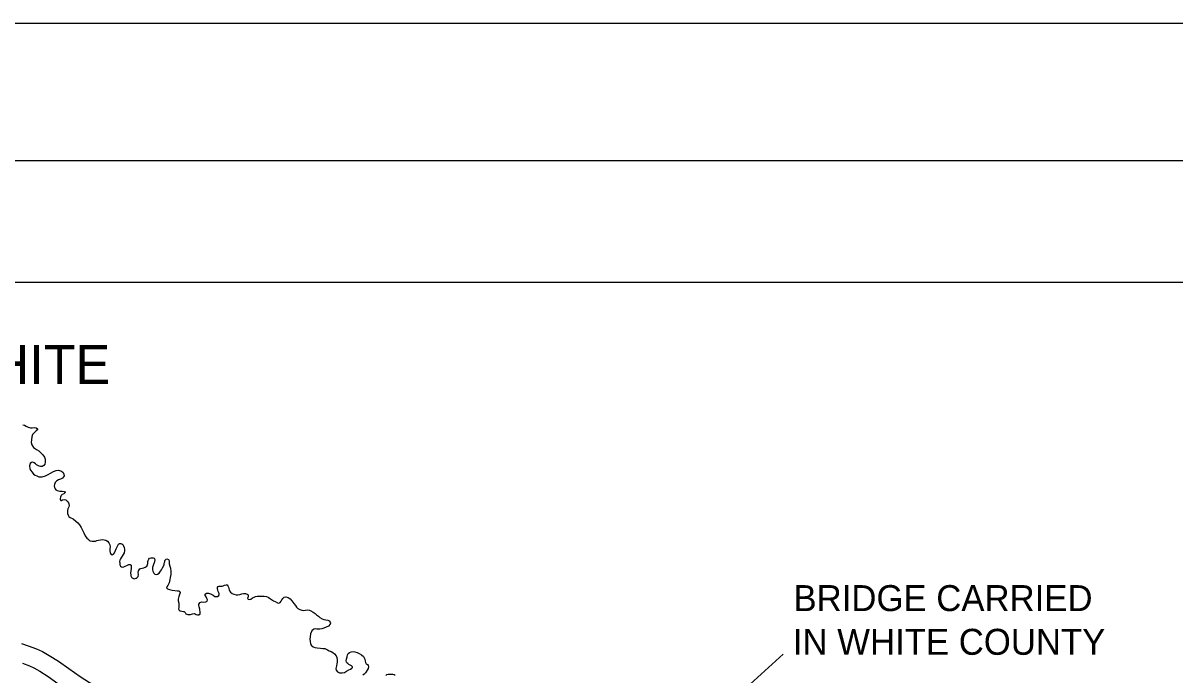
# Model space of a CAD drawing. Extents: x 1367863 to 1368197, y 380048 to 380261.
# Drawn here: x 1367891.07 to 1367923.7, y 380242.97 to 380261.43 of the extents above; entities that cross this region are included whole.
import ezdxf

# ---------------------------------------------------------------- set-up
doc = ezdxf.new("R2010")
doc.units = 0
for name, color, linetype in [('Level 10', 7, 'Continuous'), ('Level 2', 7, 'Continuous'), ('Level 30', 7, 'Continuous'), ('R_Border', 7, 'Continuous'), ('R_No Plot', 7, 'Continuous')]:
    doc.layers.add(name, color=color, linetype=linetype)

msp = doc.modelspace()

# ---------------------------------------------------------------- linework, layer by layer
at = {"layer": 'Level 10'}
for points in [[(1367891.032, 380243.854), (1367891.22, 380243.794), (1367891.456, 380243.711), (1367891.621, 380243.63), (1367891.816, 380243.521), (1367892.075, 380243.361), (1367892.365, 380243.153), (1367892.691, 380242.923), (1367892.954, 380242.757), (1367893.176, 380242.635), (1367893.378, 380242.527), (1367893.584, 380242.429), (1367893.807, 380242.311), (1367894.073, 380242.155), (1367894.149, 380242.124), (1367894.269, 380242.066), (1367894.803, 380241.868)], [(1367891.055, 380243.298), (1367891.254, 380243.229), (1367891.378, 380243.168), (1367891.551, 380243.071), (1367891.785, 380242.926), (1367892.062, 380242.728), (1367892.4, 380242.488), (1367892.689, 380242.307), (1367892.927, 380242.176), (1367893.142, 380242.061), (1367893.349, 380241.962), (1367893.553, 380241.854), (1367893.842, 380241.684), (1367893.938, 380241.646), (1367894.062, 380241.585), (1367894.621, 380241.378)]]:
    msp.add_lwpolyline(points, dxfattribs=at)
at = {"layer": 'Level 2'}
for points in [[(1367891.062, 380250.05), (1367891.116, 380250.043), (1367891.159, 380250.013), (1367891.217, 380249.985), (1367891.28, 380249.969), (1367891.329, 380249.966), (1367891.386, 380249.974), (1367891.442, 380249.966), (1367891.486, 380249.934), (1367891.482, 380249.906), (1367891.443, 380249.877), (1367891.397, 380249.835), (1367891.345, 380249.776), (1367891.321, 380249.711), (1367891.308, 380249.625), (1367891.306, 380249.553), (1367891.322, 380249.484), (1367891.373, 380249.412), (1367891.453, 380249.355), (1367891.517, 380249.312), (1367891.58, 380249.256), (1367891.63, 380249.203), (1367891.676, 380249.135), (1367891.7, 380249.075), (1367891.703, 380248.991), (1367891.694, 380248.942), (1367891.662, 380248.899), (1367891.612, 380248.869), (1367891.571, 380248.868), (1367891.529, 380248.877), (1367891.49, 380248.897), (1367891.454, 380248.92), (1367891.426, 380248.946), (1367891.39, 380248.974), (1367891.353, 380248.991), (1367891.315, 380248.988), (1367891.274, 380248.952), (1367891.256, 380248.893), (1367891.266, 380248.817), (1367891.287, 380248.763), (1367891.33, 380248.711), (1367891.372, 380248.656), (1367891.42, 380248.624), (1367891.462, 380248.606), (1367891.522, 380248.577), (1367891.612, 380248.583), (1367891.709, 380248.611), (1367891.781, 380248.642)], [(1367891.781, 380248.642), (1367891.851, 380248.679), (1367891.934, 380248.726), (1367892.014, 380248.761), (1367892.079, 380248.768), (1367892.166, 380248.74), (1367892.213, 380248.697), (1367892.23, 380248.651), (1367892.237, 380248.611), (1367892.222, 380248.574), (1367892.186, 380248.54), (1367892.133, 380248.508), (1367892.076, 380248.489), (1367892.032, 380248.47), (1367891.981, 380248.422), (1367891.964, 380248.365), (1367891.958, 380248.325), (1367891.964, 380248.276), (1367891.978, 380248.236), (1367892.005, 380248.206), (1367892.042, 380248.19), (1367892.116, 380248.174), (1367892.184, 380248.171), (1367892.234, 380248.167), (1367892.264, 380248.156), (1367892.268, 380248.137), (1367892.258, 380248.121), (1367892.224, 380248.101), (1367892.183, 380248.08), (1367892.151, 380248.051), (1367892.139, 380248.027), (1367892.131, 380248), (1367892.127, 380247.962), (1367892.123, 380247.935), (1367892.139, 380247.908), (1367892.157, 380247.905), (1367892.165, 380247.909), (1367892.187, 380247.925), (1367892.239, 380247.939), (1367892.283, 380247.923), (1367892.33, 380247.884), (1367892.362, 380247.843), (1367892.373, 380247.817), (1367892.377, 380247.769), (1367892.366, 380247.725), (1367892.345, 380247.668), (1367892.332, 380247.624), (1367892.328, 380247.584), (1367892.333, 380247.539), (1367892.352, 380247.49), (1367892.372, 380247.459), (1367892.404, 380247.429), (1367892.493, 380247.385), (1367892.566, 380247.324), (1367892.623, 380247.277), (1367892.673, 380247.222), (1367892.719, 380247.147), (1367892.756, 380247.068), (1367892.795, 380246.989), (1367892.831, 380246.911), (1367892.878, 380246.846), (1367892.905, 380246.818), (1367892.944, 380246.786), (1367892.978, 380246.769), (1367893.027, 380246.755), (1367893.077, 380246.757), (1367893.121, 380246.76), (1367893.167, 380246.771), (1367893.214, 380246.783), (1367893.268, 380246.799), (1367893.327, 380246.803), (1367893.374, 380246.799), (1367893.416, 380246.784), (1367893.469, 380246.753), (1367893.502, 380246.708), (1367893.528, 380246.657), (1367893.543, 380246.598), (1367893.531, 380246.54), (1367893.53, 380246.481), (1367893.541, 380246.437), (1367893.554, 380246.404), (1367893.571, 380246.379), (1367893.592, 380246.371), (1367893.635, 380246.391), (1367893.665, 380246.425), (1367893.714, 380246.535), (1367893.73, 380246.581), (1367893.748, 380246.615), (1367893.765, 380246.648), (1367893.778, 380246.671), (1367893.804, 380246.686), (1367893.838, 380246.692), (1367893.868, 380246.685), (1367893.895, 380246.658), (1367893.919, 380246.627), (1367893.936, 380246.575), (1367893.946, 380246.518), (1367893.947, 380246.479), (1367893.935, 380246.428), (1367893.912, 380246.38), (1367893.879, 380246.336)], [(1367893.879, 380246.336), (1367893.859, 380246.304), (1367893.832, 380246.254), (1367893.816, 380246.222), (1367893.807, 380246.185), (1367893.81, 380246.136), (1367893.818, 380246.084), (1367893.831, 380246.05), (1367893.86, 380246.025), (1367893.895, 380246.017), (1367893.928, 380246.025), (1367893.969, 380246.045), (1367894.012, 380246.071), (1367894.067, 380246.094), (1367894.095, 380246.096), (1367894.109, 380246.095), (1367894.132, 380246.076), (1367894.137, 380246.038), (1367894.133, 380245.98), (1367894.126, 380245.919), (1367894.118, 380245.849), (1367894.121, 380245.807), (1367894.127, 380245.774), (1367894.149, 380245.735), (1367894.167, 380245.714), (1367894.224, 380245.69), (1367894.274, 380245.704), (1367894.306, 380245.727), (1367894.335, 380245.758), (1367894.34, 380245.809), (1367894.335, 380245.873), (1367894.342, 380245.917), (1367894.362, 380245.949), (1367894.382, 380245.971), (1367894.413, 380245.98), (1367894.45, 380245.992), (1367894.494, 380246.004), (1367894.545, 380246.016)], [(1367894.494, 380246.004), (1367894.548, 380246.028), (1367894.574, 380246.042), (1367894.592, 380246.072), (1367894.605, 380246.12), (1367894.61, 380246.183), (1367894.616, 380246.211), (1367894.631, 380246.243), (1367894.655, 380246.275), (1367894.696, 380246.288), (1367894.759, 380246.286), (1367894.79, 380246.271), (1367894.807, 380246.235), (1367894.8, 380246.174), (1367894.771, 380246.095), (1367894.743, 380246.01), (1367894.738, 380245.947), (1367894.744, 380245.904), (1367894.777, 380245.85), (1367894.807, 380245.821), (1367894.844, 380245.808), (1367894.884, 380245.822), (1367894.927, 380245.851), (1367894.969, 380245.908), (1367894.99, 380245.948), (1367895.018, 380246.005), (1367895.059, 380246.066), (1367895.068, 380246.092), (1367895.074, 380246.132), (1367895.084, 380246.174), (1367895.093, 380246.208), (1367895.107, 380246.231), (1367895.129, 380246.251), (1367895.148, 380246.256), (1367895.188, 380246.24), (1367895.21, 380246.202), (1367895.207, 380246.166), (1367895.21, 380246.118), (1367895.233, 380246.053), (1367895.252, 380245.99), (1367895.256, 380245.898), (1367895.255, 380245.816), (1367895.243, 380245.725), (1367895.234, 380245.667), (1367895.21, 380245.579), (1367895.172, 380245.499), (1367895.144, 380245.467), (1367895.137, 380245.439), (1367895.168, 380245.408), (1367895.222, 380245.391), (1367895.292, 380245.365), (1367895.376, 380245.355), (1367895.45, 380245.35), (1367895.486, 380245.347), (1367895.513, 380245.334), (1367895.524, 380245.303), (1367895.508, 380245.243), (1367895.483, 380245.186), (1367895.468, 380245.116), (1367895.469, 380245.064), (1367895.486, 380245), (1367895.486, 380244.937), (1367895.481, 380244.879), (1367895.476, 380244.844), (1367895.49, 380244.806), (1367895.523, 380244.781), (1367895.567, 380244.773), (1367895.619, 380244.766), (1367895.634, 380244.761), (1367895.66, 380244.734), (1367895.687, 380244.699), (1367895.744, 380244.675), (1367895.82, 380244.682), (1367895.87, 380244.699), (1367895.915, 380244.707), (1367895.945, 380244.701), (1367895.975, 380244.682), (1367896.015, 380244.671), (1367896.05, 380244.674), (1367896.086, 380244.694), (1367896.09, 380244.734), (1367896.076, 380244.827), (1367896.058, 380244.896), (1367896.047, 380244.936), (1367896.055, 380244.974), (1367896.086, 380245.019), (1367896.128, 380245.043), (1367896.187, 380245.03), (1367896.246, 380245.035), (1367896.291, 380245.061), (1367896.299, 380245.091), (1367896.282, 380245.136), (1367896.256, 380245.182), (1367896.237, 380245.206), (1367896.224, 380245.227), (1367896.228, 380245.253), (1367896.273, 380245.281), (1367896.322, 380245.282), (1367896.381, 380245.264), (1367896.457, 380245.224), (1367896.507, 380245.194)], [(1367896.507, 380245.194), (1367896.55, 380245.188), (1367896.58, 380245.194), (1367896.616, 380245.216), (1367896.627, 380245.245), (1367896.625, 380245.279), (1367896.602, 380245.335), (1367896.591, 380245.371), (1367896.579, 380245.414), (1367896.58, 380245.449), (1367896.595, 380245.476), (1367896.63, 380245.486), (1367896.677, 380245.482), (1367896.713, 380245.481), (1367896.744, 380245.49), (1367896.782, 380245.511), (1367896.822, 380245.524), (1367896.852, 380245.519), (1367896.877, 380245.496), (1367896.893, 380245.454), (1367896.915, 380245.374), (1367896.919, 380245.354), (1367896.947, 380245.316), (1367896.994, 380245.275), (1367897.04, 380245.252), (1367897.106, 380245.24), (1367897.153, 380245.237), (1367897.21, 380245.246), (1367897.274, 380245.265), (1367897.321, 380245.273), (1367897.375, 380245.271), (1367897.419, 380245.252), (1367897.444, 380245.235), (1367897.453, 380245.216), (1367897.452, 380245.184), (1367897.441, 380245.161), (1367897.434, 380245.135), (1367897.445, 380245.113), (1367897.479, 380245.101), (1367897.527, 380245.118), (1367897.57, 380245.147), (1367897.614, 380245.175), (1367897.657, 380245.19), (1367897.701, 380245.2), (1367897.744, 380245.197), (1367897.795, 380245.195), (1367897.852, 380245.198), (1367897.906, 380245.2), (1367897.964, 380245.193), (1367898.011, 380245.173), (1367898.057, 380245.143), (1367898.114, 380245.108), (1367898.17, 380245.071), (1367898.209, 380245.045), (1367898.275, 380245.009), (1367898.318, 380245.005), (1367898.358, 380245.02), (1367898.387, 380245.054), (1367898.401, 380245.092), (1367898.428, 380245.137), (1367898.464, 380245.169), (1367898.516, 380245.181), (1367898.581, 380245.165), (1367898.639, 380245.125), (1367898.686, 380245.069), (1367898.743, 380244.995), (1367898.785, 380244.933), (1367898.816, 380244.887), (1367898.859, 380244.85), (1367898.913, 380244.821), (1367898.973, 380244.802), (1367899.018, 380244.796), (1367899.074, 380244.805), (1367899.135, 380244.808), (1367899.185, 380244.799), (1367899.228, 380244.779), (1367899.293, 380244.744), (1367899.348, 380244.705), (1367899.385, 380244.672), (1367899.437, 380244.631), (1367899.479, 380244.597), (1367899.541, 380244.56), (1367899.596, 380244.539), (1367899.647, 380244.532), (1367899.702, 380244.521), (1367899.74, 380244.499), (1367899.767, 380244.462), (1367899.776, 380244.434), (1367899.77, 380244.404), (1367899.723, 380244.349), (1367899.654, 380244.322), (1367899.59, 380244.295), (1367899.537, 380244.27), (1367899.476, 380244.26), (1367899.398, 380244.263), (1367899.347, 380244.269), (1367899.307, 380244.263), (1367899.252, 380244.221), (1367899.216, 380244.129), (1367899.203, 380244.049), (1367899.199, 380243.98)], [(1367899.199, 380243.98), (1367899.203, 380243.911), (1367899.215, 380243.86), (1367899.237, 380243.807), (1367899.292, 380243.768), (1367899.336, 380243.748), (1367899.401, 380243.738), (1367899.495, 380243.726), (1367899.563, 380243.719), (1367899.617, 380243.714), (1367899.657, 380243.701), (1367899.7, 380243.679), (1367899.746, 380243.654), (1367899.8, 380243.628), (1367899.843, 380243.605), (1367899.892, 380243.566), (1367899.939, 380243.508), (1367899.963, 380243.461), (1367899.973, 380243.4), (1367899.972, 380243.332), (1367899.962, 380243.285), (1367899.948, 380243.223), (1367899.936, 380243.153), (1367899.941, 380243.099), (1367899.975, 380243.056), (1367900.039, 380243.027), (1367900.108, 380243.023), (1367900.176, 380243.041), (1367900.234, 380243.075), (1367900.298, 380243.109), (1367900.346, 380243.131), (1367900.383, 380243.158), (1367900.4, 380243.176), (1367900.401, 380243.199), (1367900.376, 380243.224), (1367900.336, 380243.246), (1367900.301, 380243.262), (1367900.27, 380243.289), (1367900.245, 380243.311), (1367900.233, 380243.33), (1367900.223, 380243.363), (1367900.234, 380243.418), (1367900.251, 380243.481), (1367900.264, 380243.534), (1367900.284, 380243.576), (1367900.321, 380243.605), (1367900.366, 380243.624), (1367900.423, 380243.63), (1367900.474, 380243.621), (1367900.536, 380243.602), (1367900.597, 380243.576), (1367900.654, 380243.539), (1367900.716, 380243.488), (1367900.738, 380243.454), (1367900.753, 380243.417), (1367900.759, 380243.362), (1367900.773, 380243.318), (1367900.794, 380243.286), (1367900.826, 380243.264), (1367900.848, 380243.231), (1367900.858, 380243.193), (1367900.85, 380243.149), (1367900.823, 380243.103), (1367900.773, 380243.029), (1367900.731, 380242.989), (1367900.693, 380242.965)], [(1367901.348, 380242.956), (1367901.38, 380242.977), (1367901.411, 380242.988), (1367901.46, 380242.994), (1367901.503, 380242.99), (1367901.545, 380242.99), (1367901.584, 380242.982), (1367901.616, 380242.957)]]:
    msp.add_lwpolyline(points, dxfattribs=at)
at = {"layer": 'Level 30'}
msp.add_line((1367909.89, 380241.092), (1367912.603, 380243.56), dxfattribs=at)
at = {"layer": 'R_Border'}
msp.add_line((1367875.8, 380257.536), (1368191.969, 380257.536), dxfattribs=at)
at = {"layer": 'R_No Plot'}
for p in [(1367863.388, 380261.431), (1367863.4, 380261.431)]:
    msp.add_line(p, (1368196.721, 380261.431), dxfattribs=at)
for points in [[(1367863.393, 380261.431), (1368196.721, 380261.431), (1368196.721, 380048.101), (1367863.393, 380048.101)], [(1367878.711, 380254.093), (1367937.876, 380254.093), (1367937.876, 380187.495), (1367878.711, 380187.495)]]:
    msp.add_lwpolyline(points, close=True, dxfattribs=at)

# ---------------------------------------------------------------- texts
at = {"layer": 'Level 30'}
for s, height, p in [('WHITE', 1.1032, (1367888.79, 380251.211)), ('BRIDGE CARRIED', 0.73549, (1367912.894, 380244.776)), ('IN WHITE COUNTY', 0.73549, (1367912.876, 380243.538))]:
    msp.add_text(s, height=height, dxfattribs=at).set_placement(p)

doc.saveas('drawing.dxf')
